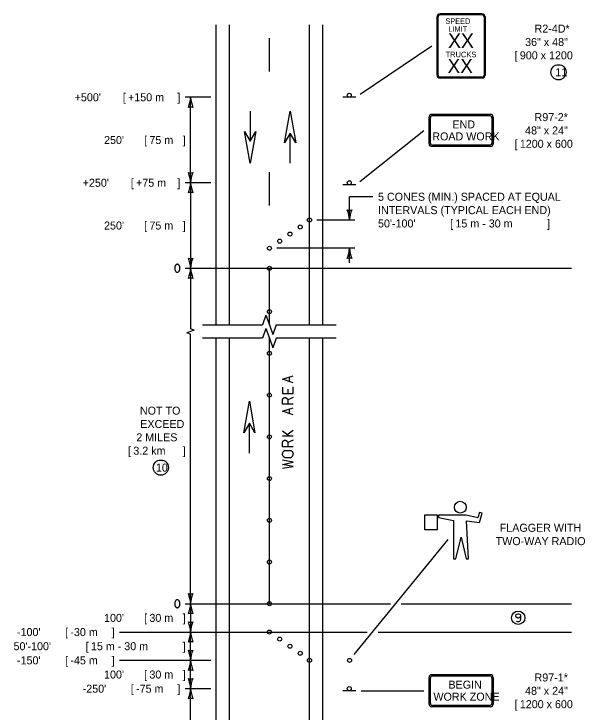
# Model space of a CAD drawing. Extents: x 49987.3 to 50021, y 49987.6 to 50011.4.
# Drawn here: x 49987.32 to 49991.6, y 50004.82 to 50010.05 of the extents above; entities that cross this region are included whole.
import ezdxf

# ---------------------------------------------------------------- set-up
doc = ezdxf.new("R2010")
doc.units = 0
for name, color, linetype in [('Level 1', 7, 'Continuous'), ('Level 2', 7, 'Continuous'), ('Level 3', 7, 'Continuous'), ('Level 6', 7, 'Continuous')]:
    doc.layers.add(name, color=color, linetype=linetype)

msp = doc.modelspace()

# ---------------------------------------------------------------- linework, layer by layer
at = {"layer": 'Level 1'}
for p, q in [((49990.8254, 50010.0465), (49990.5104, 50010.0465)), ((49990.8254, 50010.0389), (49990.5104, 50010.0389)), ((49990.4879, 50009.5891), (49990.4879, 50010.024)), ((49990.4955, 50009.5891), (49990.4955, 50010.024)), ((49990.8403, 50010.024), (49990.8403, 50009.5891)), ((49990.8479, 50010.024), (49990.8479, 50009.5891)), ((49988.8324, 50007.7182), (49988.8324, 50009.9659)), ((49988.9324, 50007.7182), (49988.9324, 50009.9659)), ((49989.5324, 50007.7182), (49989.5324, 50009.9659)), ((49989.6323, 50007.7182), (49989.6323, 50009.9659)), ((49989.2324, 50009.616), (49989.2324, 50009.8659)), ((49990.6714, 50009.8488), (49990.6714, 50009.8488)), ((49990.8254, 50009.5742), (49990.5104, 50009.5742)), ((49990.8254, 50009.5666), (49990.5104, 50009.5666)), ((49989.8783, 50009.4225), (49989.7825, 50009.4225)), ((49989.0874, 50009.319), (49989.0874, 50009.0929)), ((49989.0877, 50009.319), (49989.0877, 50009.0929)), ((49990.4279, 50009.0739), (49990.4279, 50009.2739)), ((49990.4379, 50009.0789), (49990.4379, 50009.2689)), ((49990.8879, 50009.2939), (49990.4479, 50009.2939)), ((49990.8829, 50009.2839), (49990.4529, 50009.2839)), ((49990.8979, 50009.2689), (49990.8979, 50009.0789)), ((49990.9079, 50009.2739), (49990.9079, 50009.0739)), ((49989.3871, 50008.9287), (49989.3871, 50009.1545)), ((49989.3874, 50008.9287), (49989.3874, 50009.1545)), ((49990.8878, 50009.0538), (49990.4478, 50009.0538)), ((49990.8829, 50009.0639), (49990.4529, 50009.0639)), ((49989.2324, 50008.6118), (49989.2324, 50008.8617)), ((49989.8783, 50008.7665), (49989.7824, 50008.7665)), ((49989.2324, 50007.7167), (49989.2324, 50008.1415)), ((49988.8324, 50001.0011), (49988.8324, 50007.6183)), ((49988.9323, 50001.0011), (49988.9324, 50007.6183)), ((49989.2324, 50005.6287), (49989.2324, 50007.6168)), ((49989.5323, 50001.0011), (49989.5324, 50007.6183)), ((49989.6323, 50001.0011), (49989.6323, 50007.6183)), ((49989.0821, 50006.7559), (49989.0821, 50006.982)), ((49989.0824, 50006.7559), (49989.0824, 50006.982)), ((49990.3962, 50006.1813), (49990.3962, 50006.2938)), ((49990.3962, 50006.2938), (49990.488, 50006.2938)), ((49990.488, 50006.2938), (49990.488, 50006.1813)), ((49990.7052, 50006.2932), (49990.4982, 50006.2932)), ((49990.4982, 50006.2932), (49990.4982, 50006.2746)), ((49990.4982, 50006.2746), (49990.6108, 50006.2524)), ((49990.792, 50006.2732), (49990.7052, 50006.2932)), ((49990.8047, 50006.3127), (49990.792, 50006.2732)), ((49990.8266, 50006.3072), (49990.8047, 50006.3127)), ((49990.8067, 50006.2383), (49990.8266, 50006.3072)), ((49990.6108, 50006.2524), (49990.6108, 50005.966)), ((49990.7238, 50005.966), (49990.7091, 50006.2494)), ((49990.7091, 50006.2494), (49990.8067, 50006.2383)), ((49990.488, 50006.1813), (49990.3962, 50006.1813)), ((49990.6289, 50005.966), (49990.6672, 50006.1274)), ((49990.6672, 50006.1274), (49990.7055, 50005.966)), ((49990.6108, 50005.966), (49990.6289, 50005.966)), ((49990.7055, 50005.966), (49990.7238, 50005.966)), ((49990.4278, 50004.8772), (49990.4278, 50005.0772)), ((49990.4378, 50004.8822), (49990.4378, 50005.0722)), ((49990.8878, 50005.0972), (49990.4478, 50005.0972)), ((49990.8828, 50005.0872), (49990.4528, 50005.0872)), ((49990.8978, 50005.0722), (49990.8978, 50004.8822)), ((49990.9078, 50005.0772), (49990.9078, 50004.8772)), ((49989.8782, 50004.9772), (49989.7823, 50004.9772)), ((49990.8877, 50004.8572), (49990.4477, 50004.8572)), ((49990.8828, 50004.8672), (49990.4528, 50004.8672))]:
    msp.add_line(p, q, dxfattribs=at)
for points in [[(49989.3454, 50009.0823), (49989.3871, 50009.3186), (49989.429, 50009.0823), (49989.3871, 50009.1545)], [(49989.1295, 50009.1654), (49989.0877, 50008.9287), (49989.0459, 50009.1654), (49989.0877, 50009.0931)], [(49989.0404, 50006.9095), (49989.0821, 50007.1462), (49989.124, 50006.9095), (49989.0821, 50006.9817)]]:
    msp.add_lwpolyline(points, close=True, dxfattribs=at)
for points in [[(49990.8045, 50006.3126), (49990.8047, 50006.3127)], [(49990.806, 50006.2386), (49990.8069, 50006.2395)], [(49990.4877, 50006.1813), (49990.488, 50006.1817)]]:
    msp.add_lwpolyline(points, dxfattribs=at)
for centre, radius in [((49989.8303, 50009.4379), 0.0152), ((49989.8303, 50008.782), 0.0152), ((49989.5324, 50008.5037), 0.015), ((49989.4628, 50008.4507), 0.015), ((49989.386, 50008.3977), 0.015), ((49989.3092, 50008.3446), 0.015), ((49989.2324, 50008.2916), 0.015), ((49989.2324, 50008.1415), 0.015), ((49989.2324, 50007.8163), 0.015), ((49989.2324, 50007.5038), 0.015), ((49989.2324, 50007.1913), 0.015), ((49989.2324, 50006.8788), 0.015), ((49989.2324, 50006.5663), 0.015), ((49990.6616, 50006.352), 0.0442), ((49989.2324, 50006.2538), 0.015), ((49989.2324, 50005.9413), 0.015), ((49989.2324, 50005.6288), 0.015), ((49989.2324, 50005.4166), 0.015), ((49989.3092, 50005.3636), 0.015), ((49989.386, 50005.3106), 0.015), ((49989.4628, 50005.2575), 0.015), ((49989.5324, 50005.2045), 0.015), ((49989.8323, 50005.2045), 0.0152), ((49989.8302, 50004.9926), 0.0152)]:
    msp.add_circle(centre, radius, dxfattribs=at)
for centre, radius, start, end in [((49990.5104, 50010.024), 0.0225, 90, 180), ((49990.5104, 50010.024), 0.0149, 90, 180), ((49990.8254, 50010.024), 0.0225, 0, 90), ((49990.8254, 50010.024), 0.0149, 0, 90), ((49990.5104, 50009.5891), 0.0225, 180, 270), ((49990.5104, 50009.5891), 0.0149, 180, 270), ((49990.8254, 50009.5891), 0.0225, 270, 0), ((49990.8254, 50009.5891), 0.0149, 270, 0), ((49990.4479, 50009.2739), 0.02, 90, 180), ((49990.4529, 50009.2689), 0.015, 90, 180), ((49990.8829, 50009.2689), 0.015, 360, 90), ((49990.8879, 50009.2739), 0.02, 360, 90), ((49990.4478, 50009.0739), 0.02, 180, 270), ((49990.4529, 50009.0789), 0.015, 180, 270), ((49990.8829, 50009.0789), 0.015, 270, 360), ((49990.8878, 50009.0739), 0.02, 270, 360), ((49990.4478, 50005.0772), 0.02, 90, 180), ((49990.4528, 50005.0722), 0.015, 90, 180), ((49990.8828, 50005.0722), 0.015, 0, 90), ((49990.8878, 50005.0772), 0.02, 0, 90), ((49990.4477, 50004.8772), 0.02, 180, 270), ((49990.4528, 50004.8822), 0.015, 180, 270), ((49990.8828, 50004.8822), 0.015, 270, 0), ((49990.8877, 50004.8772), 0.02, 270, 360)]:
    msp.add_arc(centre, radius, start, end, dxfattribs=at)
at = {"layer": 'Level 2'}
for p, q in [((49989.3829, 50007.2927), (49989.3829, 50007.3274)), ((49989.3697, 50007.2366), (49989.3697, 50007.2039)), ((49989.41, 50007.1737), (49989.369, 50007.1554)), ((49989.3829, 50007.0527), (49989.3829, 50007.0874)), ((49989.381, 50006.8839), (49989.33, 50006.9223)), ((49989.3646, 50006.8965), (49989.41, 50006.9292)), ((49989.41, 50006.8839), (49989.33, 50006.8839)), ((49989.41, 50006.8537), (49989.369, 50006.8354)), ((49989.33, 50006.7472), (49989.33, 50006.7535)), ((49989.3476, 50006.7768), (49989.3936, 50006.7768)), ((49989.41, 50006.7472), (49989.41, 50006.7535)), ((49989.3476, 50006.7239), (49989.3936, 50006.7239))]:
    msp.add_line(p, q, dxfattribs=at)
for points in [[(49988.5426, 50008.1115), (49988.5447, 50008.1116), (49988.5468, 50008.1121), (49988.5488, 50008.113), (49988.5507, 50008.1141), (49988.5526, 50008.1155), (49988.5543, 50008.1172), (49988.5559, 50008.1192), (49988.5574, 50008.1214), (49988.5587, 50008.1239), (49988.5598, 50008.1265), (49988.5608, 50008.1293), (49988.5615, 50008.1322), (49988.5621, 50008.1352), (49988.5624, 50008.1383), (49988.5625, 50008.1415), (49988.5624, 50008.1446), (49988.5621, 50008.1477), (49988.5615, 50008.1507), (49988.5608, 50008.1537), (49988.5598, 50008.1565), (49988.5587, 50008.1591), (49988.5574, 50008.1616), (49988.5559, 50008.1638), (49988.5543, 50008.1657), (49988.5526, 50008.1675), (49988.5507, 50008.1689), (49988.5488, 50008.17), (49988.5468, 50008.1708), (49988.5447, 50008.1713), (49988.5426, 50008.1715), (49988.5406, 50008.1713), (49988.5385, 50008.1708), (49988.5365, 50008.17), (49988.5346, 50008.1689), (49988.5327, 50008.1675), (49988.531, 50008.1657), (49988.5294, 50008.1638), (49988.5279, 50008.1616), (49988.5266, 50008.1591), (49988.5255, 50008.1565), (49988.5245, 50008.1537), (49988.5238, 50008.1507), (49988.5232, 50008.1477), (49988.5229, 50008.1446), (49988.5228, 50008.1415), (49988.5229, 50008.1383), (49988.5232, 50008.1352), (49988.5238, 50008.1322), (49988.5245, 50008.1293), (49988.5255, 50008.1265), (49988.5266, 50008.1239), (49988.5279, 50008.1214), (49988.5294, 50008.1192), (49988.531, 50008.1172), (49988.5327, 50008.1155), (49988.5346, 50008.1141), (49988.5365, 50008.113), (49988.5385, 50008.1121), (49988.5406, 50008.1116), (49988.5426, 50008.1115)], [(49989.41, 50007.2839), (49989.33, 50007.3103), (49989.41, 50007.3362)], [(49989.33, 50007.2499), (49989.33, 50007.2039), (49989.41, 50007.2039), (49989.41, 50007.253)], [(49989.41, 50007.1239), (49989.33, 50007.1239), (49989.33, 50007.156), (49989.3331, 50007.1655), (49989.3457, 50007.1737), (49989.3533, 50007.1737), (49989.3659, 50007.1661), (49989.369, 50007.156), (49989.369, 50007.1239)], [(49989.41, 50007.0439), (49989.33, 50007.0703), (49989.41, 50007.0962)], [(49989.41, 50006.8039), (49989.33, 50006.8039), (49989.33, 50006.836), (49989.3331, 50006.8455), (49989.3457, 50006.8537), (49989.3533, 50006.8537), (49989.3659, 50006.8461), (49989.369, 50006.836), (49989.369, 50006.8039)], [(49989.3476, 50006.7768), (49989.3448, 50006.7753), (49989.342, 50006.7735), (49989.3395, 50006.7714), (49989.3373, 50006.769), (49989.3353, 50006.7665), (49989.3335, 50006.7637), (49989.3321, 50006.7608), (49989.331, 50006.7577), (49989.3302, 50006.7546), (49989.33, 50006.7535)], [(49989.3476, 50006.7239), (49989.3448, 50006.7254), (49989.342, 50006.7272), (49989.3395, 50006.7293), (49989.3373, 50006.7317), (49989.3353, 50006.7342), (49989.3335, 50006.737), (49989.3321, 50006.7399), (49989.331, 50006.743), (49989.3302, 50006.7461), (49989.33, 50006.7472)], [(49989.3936, 50006.7768), (49989.3966, 50006.7748), (49989.3994, 50006.7725), (49989.4019, 50006.77), (49989.4042, 50006.7672), (49989.4061, 50006.7641), (49989.4077, 50006.7609), (49989.409, 50006.7576), (49989.4099, 50006.7541), (49989.41, 50006.7535)], [(49989.3936, 50006.7239), (49989.3966, 50006.7259), (49989.3994, 50006.7281), (49989.4019, 50006.7307), (49989.4042, 50006.7335), (49989.4061, 50006.7365), (49989.4077, 50006.7398), (49989.409, 50006.7431), (49989.4099, 50006.7466), (49989.41, 50006.7472)], [(49989.33, 50006.6439), (49989.41, 50006.6565), (49989.33, 50006.6729), (49989.41, 50006.6892), (49989.33, 50006.7031)], [(49988.5426, 50005.5987), (49988.5447, 50005.5989), (49988.5467, 50005.5994), (49988.5487, 50005.6002), (49988.5507, 50005.6013), (49988.5525, 50005.6027), (49988.5543, 50005.6045), (49988.5559, 50005.6064), (49988.5573, 50005.6087), (49988.5587, 50005.6111), (49988.5598, 50005.6137), (49988.5607, 50005.6165), (49988.5615, 50005.6195), (49988.562, 50005.6225), (49988.5623, 50005.6256), (49988.5624, 50005.6287), (49988.5623, 50005.6319), (49988.562, 50005.635), (49988.5615, 50005.638), (49988.5607, 50005.6409), (49988.5598, 50005.6437), (49988.5587, 50005.6464), (49988.5573, 50005.6488), (49988.5559, 50005.651), (49988.5543, 50005.653), (49988.5525, 50005.6547), (49988.5507, 50005.6561), (49988.5487, 50005.6572), (49988.5467, 50005.6581), (49988.5447, 50005.6586), (49988.5426, 50005.6587), (49988.5405, 50005.6586), (49988.5385, 50005.6581), (49988.5365, 50005.6572), (49988.5345, 50005.6561), (49988.5327, 50005.6547), (49988.5309, 50005.653), (49988.5293, 50005.651), (49988.5279, 50005.6488), (49988.5266, 50005.6464), (49988.5254, 50005.6437), (49988.5245, 50005.6409), (49988.5237, 50005.638), (49988.5232, 50005.635), (49988.5229, 50005.6319), (49988.5228, 50005.6287), (49988.5229, 50005.6256), (49988.5232, 50005.6225), (49988.5237, 50005.6195), (49988.5245, 50005.6165), (49988.5254, 50005.6137), (49988.5266, 50005.6111), (49988.5279, 50005.6087), (49988.5293, 50005.6064), (49988.5309, 50005.6045), (49988.5327, 50005.6027), (49988.5345, 50005.6013), (49988.5365, 50005.6002), (49988.5385, 50005.5994), (49988.5405, 50005.5989), (49988.5426, 50005.5987)], [(49991.1127, 50005.5321), (49991.1051, 50005.5245), (49991.0976, 50005.5217), (49991.0928, 50005.5212), (49991.0857, 50005.5245), (49991.0805, 50005.5292), (49991.0782, 50005.5368), (49991.0782, 50005.5392), (49991.0801, 50005.5472), (49991.0853, 50005.5514), (49991.0928, 50005.5538), (49991.0976, 50005.5538), (49991.1046, 50005.5514), (49991.1103, 50005.5472), (49991.1127, 50005.5392), (49991.1127, 50005.5217), (49991.1117, 50005.5155), (49991.1098, 50005.5023), (49991.1075, 50005.4981), (49991.1046, 50005.4957), (49991.0976, 50005.4938), (49991.0928, 50005.4938), (49991.0857, 50005.4957), (49991.0829, 50005.4981)]]:
    msp.add_lwpolyline(points, dxfattribs=at)
for centre, radius in [((49991.3971, 50009.6097), 0.0569), ((49988.4191, 50006.6483), 0.0569), ((49991.0954, 50005.5238), 0.05)]:
    msp.add_circle(centre, radius, dxfattribs=at)
at = {"layer": 'Level 3'}
for p, q in [((49989.9114, 50009.4448), (49990.4479, 50009.8065)), ((49988.7924, 50009.4225), (49988.6025, 50009.4225)), ((49988.6425, 50008.782), (49988.6425, 50009.4225)), ((49989.9096, 50008.7915), (49990.3879, 50009.1739)), ((49988.7925, 50008.782), (49988.6025, 50008.782)), ((49988.6425, 50008.782), (49988.6425, 50008.1415)), ((49989.8323, 50008.5037), (49989.8323, 50008.6771)), ((49990.0056, 50008.6771), (49989.8323, 50008.6771)), ((49989.5874, 50008.5037), (49989.8723, 50008.5037)), ((49989.8723, 50008.2916), (49989.2874, 50008.2916)), ((49989.8323, 50008.1815), (49989.8323, 50008.2916)), ((49988.6025, 50008.1415), (49991.4955, 50008.1415)), ((49988.6425, 50008.1415), (49988.6425, 50007.6876)), ((49988.6699, 50007.6779), (49988.6425, 50007.6876)), ((49988.6699, 50007.6779), (49988.6425, 50007.6682)), ((49988.6425, 50007.6682), (49988.6151, 50007.6585)), ((49988.6425, 50007.6488), (49988.6151, 50007.6585)), ((49988.6425, 50005.6287), (49988.6425, 50007.6488)), ((49989.8672, 50005.2473), (49990.5708, 50006.1092)), ((49988.6024, 50005.6287), (49990.1386, 50005.6287)), ((49988.6425, 50005.6287), (49988.6425, 50005.4166)), ((49990.2186, 50005.6287), (49991.4954, 50005.6287)), ((49988.1106, 50005.4166), (49989.9655, 50005.4166)), ((49988.6425, 50005.2045), (49988.6425, 50005.4166)), ((49990.0455, 50005.4166), (49991.4954, 50005.4166)), ((49988.7924, 50005.2045), (49988.1106, 50005.2045)), ((49988.6425, 50001.3045), (49988.6425, 50005.2045)), ((49988.7924, 50004.9924), (49988.6024, 50004.9924)), ((49989.9182, 50004.9772), (49990.3878, 50004.9772))]:
    msp.add_line(p, q, dxfattribs=at)
for centre, radius, start, end in [((49988.4203, 50009.4317), 0.2223, 337.456, 357.6395), ((49988.8752, 50009.434), 0.233, 182.8273, 202.0772), ((49988.6425, 50009.2943), 0.0548, 72.1388, 107.8612), ((49988.6425, 50008.9102), 0.0548, 252.1388, 287.8612), ((49988.4098, 50008.7705), 0.233, 2.8273, 22.0772), ((49988.8646, 50008.7729), 0.2223, 157.456, 177.6395), ((49988.4203, 50008.7912), 0.2223, 337.456, 357.6395), ((49988.8752, 50008.7935), 0.233, 182.8273, 202.0772), ((49988.6425, 50008.6538), 0.0548, 72.1388, 107.8612), ((49989.8323, 50008.6319), 0.0548, 252.1388, 287.8612), ((49989.5996, 50008.4922), 0.233, 2.8273, 22.0772), ((49990.0544, 50008.4945), 0.2223, 157.456, 177.6395), ((49989.6102, 50008.3008), 0.2223, 337.456, 357.6395), ((49990.065, 50008.3031), 0.233, 182.8273, 202.0772), ((49988.6425, 50008.2697), 0.0548, 252.1388, 287.8612), ((49988.4098, 50008.13), 0.233, 2.8273, 22.0772), ((49988.8646, 50008.1323), 0.2223, 157.456, 177.6395), ((49989.8323, 50008.1634), 0.0548, 72.1388, 107.8612), ((49988.4204, 50008.1506), 0.2223, 337.456, 357.6395), ((49988.8752, 50008.153), 0.233, 182.8273, 202.0772), ((49988.6425, 50008.0133), 0.0548, 72.1388, 107.8612), ((49988.6425, 50005.7569), 0.0548, 252.1388, 287.8612), ((49988.4098, 50005.6172), 0.233, 2.8273, 22.0772), ((49988.8646, 50005.6196), 0.2223, 157.456, 177.6395), ((49988.4204, 50005.6379), 0.2223, 337.456, 357.6395), ((49988.8752, 50005.6402), 0.233, 182.8273, 202.0772), ((49988.6425, 50005.5005), 0.0548, 72.1388, 107.8612), ((49988.6425, 50005.5448), 0.0548, 252.1388, 287.8612), ((49988.4098, 50005.4051), 0.233, 2.8273, 22.0772), ((49988.8646, 50005.4075), 0.2223, 157.456, 177.6395), ((49988.4203, 50005.4258), 0.2223, 337.4581, 357.6416), ((49988.8752, 50005.4281), 0.233, 182.8294, 202.0793), ((49988.6425, 50005.2884), 0.0548, 72.1409, 107.8633), ((49988.6424, 50005.3327), 0.0548, 252.1647, 287.887), ((49988.4098, 50005.1929), 0.233, 2.8531, 22.103), ((49988.8646, 50005.1955), 0.2223, 157.4818, 177.6654), ((49988.4203, 50005.2137), 0.2223, 337.4581, 357.6416), ((49988.8752, 50005.216), 0.233, 182.8294, 202.0793), ((49988.6425, 50005.0763), 0.0548, 72.1409, 107.8633), ((49988.6424, 50005.1206), 0.0548, 252.1647, 287.887), ((49988.4098, 50004.9808), 0.233, 2.8531, 22.103), ((49988.8646, 50004.9834), 0.2223, 157.4818, 177.6654), ((49988.4203, 50005.0016), 0.2223, 337.4581, 357.6416), ((49988.8752, 50005.0039), 0.233, 182.8294, 202.0793), ((49988.6425, 50004.8642), 0.0548, 72.1409, 107.8633)]:
    msp.add_arc(centre, radius, start, end, dxfattribs=at)
at = {"layer": 'Level 6'}
for p, q in [((49989.2061, 50007.7914), (49989.1801, 50007.7182)), ((49989.2061, 50007.7914), (49989.2319, 50007.7182)), ((49988.7324, 50007.7182), (49989.1801, 50007.7182)), ((49989.2061, 50007.6913), (49989.1801, 50007.6183)), ((49989.2061, 50007.6913), (49989.2319, 50007.6183)), ((49989.2319, 50007.7182), (49989.2578, 50007.6451)), ((49989.2836, 50007.7182), (49989.2578, 50007.6451)), ((49989.2836, 50007.7182), (49989.7323, 50007.7182)), ((49989.1801, 50007.6183), (49988.7324, 50007.6183)), ((49989.2319, 50007.6183), (49989.2578, 50007.5452)), ((49989.2836, 50007.6183), (49989.2578, 50007.5452)), ((49989.7323, 50007.6183), (49989.2836, 50007.6183))]:
    msp.add_line(p, q, dxfattribs=at)

# ---------------------------------------------------------------- texts
at = {"layer": 'Level 1'}
for s, height, p in [('SPEED', 0.04121, (49990.5502, 50009.9724)), ('LIMIT', 0.04162, (49990.572, 50009.9129)), ('XX', 0.10831, (49990.5702, 50009.7919)), ('TRUCKS', 0.04183, (49990.5518, 50009.7217)), ('XX', 0.10679, (49990.5657, 50009.6035)), ('BEGIN', 0.06, (49990.573, 50004.9926)), ('WORK ZONE', 0.06, (49990.4606, 50004.9026))]:
    msp.add_text(s, height=height, dxfattribs=at).set_placement(p)
for s, p in [('END', (49990.6027, 50009.1892)), ('ROAD WORK', (49990.452, 50009.0992))]:
    msp.add_text(s, height=0.06, rotation=360, dxfattribs=at).set_placement(p)
at = {"layer": 'Level 2'}
for s, height, p in [('R2-4D*', 0.06, (49991.2178, 50009.9065)), ('36" x 48"', 0.06, (49991.147, 50009.8065)), ('[', 0.06, (49991.0678, 50009.7065)), ('900 x 1200', 0.06, (49991.1075, 50009.7065)), ('11', 0.06, (49991.373, 50009.5797)), ("+500' ", 0.05999, (49987.7741, 50009.3925)), ('[', 0.06, (49988.134, 50009.3925)), ('+150 m', 0.05999, (49988.1737, 50009.3925)), (']', 0.06, (49988.5426, 50009.3925)), ('R97-2*', 0.05999, (49991.2178, 50009.2439)), ('48" x 24"', 0.05999, (49991.147, 50009.1439)), ("250' ", 0.05999, (49987.9941, 50009.0723)), ('[', 0.06, (49988.294, 50009.0723)), ('75 m', 0.05999, (49988.3337, 50009.0723)), (']', 0.06, (49988.5826, 50009.0723)), ('[', 0.06, (49991.0679, 50009.0439)), ('1200 x 600', 0.05999, (49991.1075, 50009.0439)), ("+250' ", 0.05999, (49987.8341, 50008.752)), ('[', 0.06, (49988.194, 50008.752)), ('+75 m', 0.05999, (49988.2337, 50008.752)), (']', 0.06, (49988.5426, 50008.752)), ('5 CONES (MIN.) SPACED AT EQUAL ', 0.059993, (49990.0456, 50008.6471)), ('INTERVALS (TYPICAL EACH END)', 0.059993, (49990.0456, 50008.5471)), ("250' ", 0.05999, (49987.9941, 50008.4318)), ('[', 0.06, (49988.294, 50008.4318)), ('75 m', 0.05999, (49988.3337, 50008.4318)), (']', 0.06, (49988.5826, 50008.4318)), ("50'-100' ", 0.05999, (49990.0456, 50008.4471)), ('[', 0.06, (49990.5856, 50008.4471)), ('15 m - 30 m', 0.059993, (49990.6252, 50008.4471)), (']', 0.06, (49991.3121, 50008.4471)), ('NOT TO', 0.06, (49988.2628, 50007.0451)), ('EXCEED', 0.06, (49988.2652, 50006.9451)), ('2 MILES', 0.06, (49988.2356, 50006.8451)), ('[', 0.06, (49988.1735, 50006.7451)), ('3.2 km', 0.06, (49988.2132, 50006.7451)), (']', 0.06, (49988.5826, 50006.7451)), ('10', 0.06, (49988.3822, 50006.6183)), ('FLAGGER WITH', 0.06, (49990.9568, 50006.1677)), ('TWO-WAY RADIO', 0.06, (49990.9266, 50006.0677)), ("100' ", 0.05999, (49987.994, 50005.4927)), ('[', 0.06, (49988.294, 50005.4927)), ('30 m', 0.05999, (49988.3337, 50005.4927)), (']', 0.06, (49988.5826, 50005.4927)), ("-100' ", 0.05999, (49987.3422, 50005.3866)), ('[', 0.06, (49987.7021, 50005.3866)), ('-30 m', 0.05999, (49987.7418, 50005.3866)), (']', 0.06, (49988.0507, 50005.3866)), ("50'-100' ", 0.05999, (49987.3162, 50005.2806)), ('[', 0.06, (49987.8561, 50005.2806)), ('15 m - 30 m', 0.059993, (49987.8958, 50005.2806)), (']', 0.06, (49988.5826, 50005.2806)), ("-150' ", 0.05999, (49987.3422, 50005.1745)), ('[', 0.06, (49987.7021, 50005.1745)), ('-45 m', 0.05999, (49987.7418, 50005.1745)), (']', 0.06, (49988.0507, 50005.1745)), ("100' ", 0.05999, (49987.9941, 50005.0685)), ('[', 0.06, (49988.294, 50005.0685)), ('30 m', 0.05999, (49988.3337, 50005.0685)), (']', 0.06, (49988.5826, 50005.0685)), ('R97-1*', 0.05999, (49991.2178, 50005.0464)), ("-250' ", 0.05999, (49987.8341, 50004.9624)), ('[', 0.06, (49988.194, 50004.9624)), ('-75 m', 0.05999, (49988.2337, 50004.9624)), (']', 0.06, (49988.5426, 50004.9624)), ('48" x 24"', 0.05999, (49991.1469, 50004.9464)), ('[', 0.06, (49991.0678, 50004.8464)), ('1200 x 600', 0.05999, (49991.1075, 50004.8464))]:
    msp.add_text(s, height=height, dxfattribs=at).set_placement(p)

doc.saveas('drawing.dxf')
